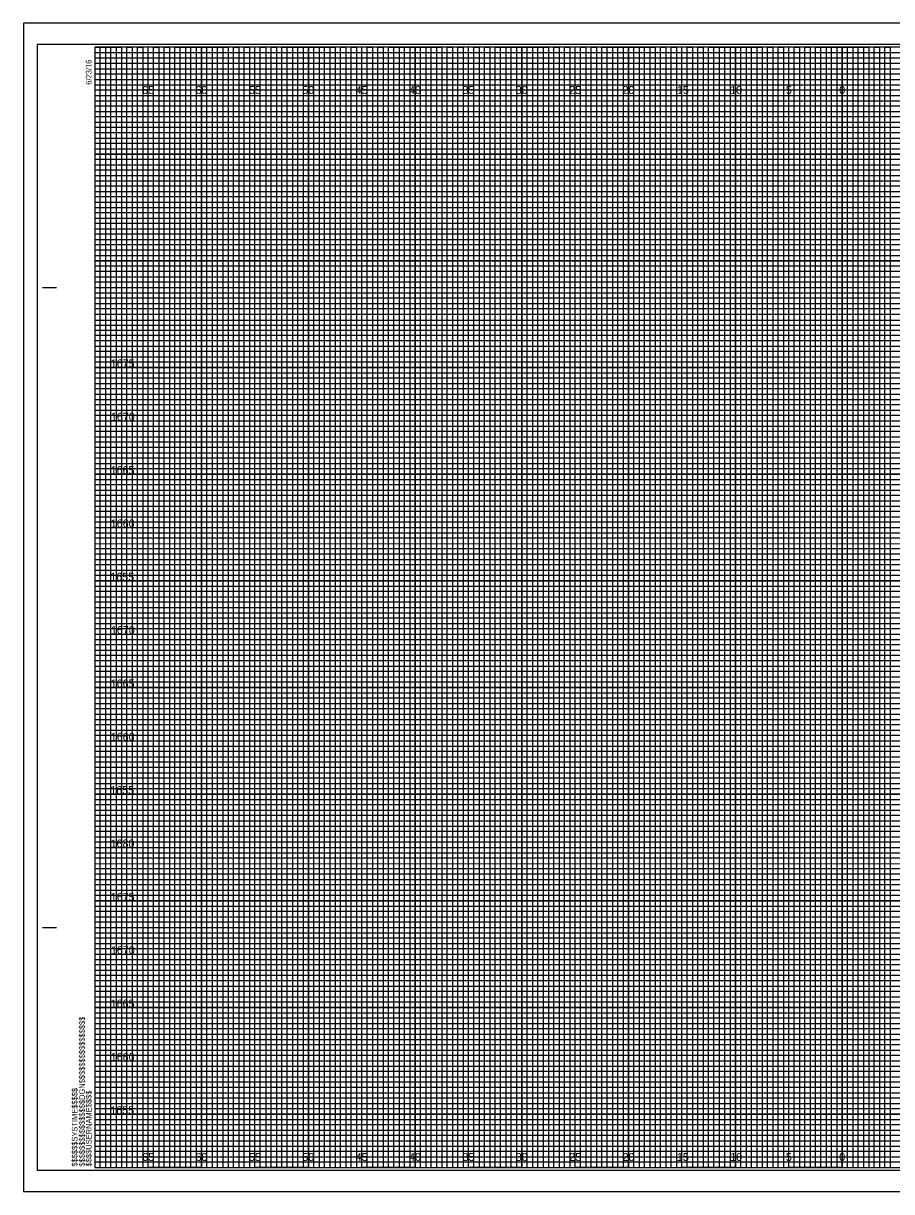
# Model space of a CAD drawing. Extents: x -73 to 95, y 6 to 446.
# Drawn here: x -73.1 to 8.2, y 116.1 to 225.6 of the extents above; entities that cross this region are included whole.
import ezdxf

# ---------------------------------------------------------------- set-up
doc = ezdxf.new("R2010")
doc.units = 0
for name, color, linetype in [('Exist CMT Alignment Centerline', 7, 'Continuous'), ('Prop Horizontal Alignment', 7, 'Continuous'), ('Prop XS DDE', 7, 'Continuous'), ('Scratch_Level_3', 7, 'Continuous'), ('Sheet Cross Section CELL', 7, 'Continuous'), ('Sheet Cross Section Grid Minor 1 CELL', 7, 'Continuous'), ('Sheet Cross Section Grid Minor 2 CELL', 7, 'Continuous'), ('Sheet Cutting Line CELL', 7, 'Continuous'), ('Sheet DOT Grid CELL', 7, 'Continuous'), ('Sheet Plot Border Inside CELL', 7, 'Continuous'), ('Sheet Plot Border Outside CELL', 7, 'Continuous')]:
    doc.layers.add(name, color=color, linetype=linetype)

msp = doc.modelspace()

# ---------------------------------------------------------------- linework, layer by layer
at = {"layer": 'Exist CMT Alignment Centerline'}
for p, q in [((-61.4, 223.4), (-66.4, 223.4)), ((-61.4, 118.4), (-61.4, 223.4)), ((-51.4, 223.4), (-56.4, 223.4)), ((-56.4, 223.4), (-56.4, 118.4)), ((-51.4, 118.4), (-51.4, 223.4)), ((-41.4, 223.4), (-46.4, 223.4)), ((-46.4, 223.4), (-46.4, 118.4)), ((-41.4, 118.4), (-41.4, 223.4)), ((-31.4, 223.4), (-36.4, 223.4)), ((-36.4, 223.4), (-36.4, 118.4)), ((-31.4, 118.4), (-31.4, 223.4)), ((-21.4, 223.4), (-26.4, 223.4)), ((-26.4, 223.4), (-26.4, 118.4)), ((-21.4, 118.4), (-21.4, 223.4)), ((-11.4, 223.4), (-16.4, 223.4)), ((-16.4, 223.4), (-16.4, 118.4)), ((-11.4, 118.4), (-11.4, 223.4)), ((-1.4, 223.4), (-6.4, 223.4)), ((-6.4, 223.4), (-6.4, 118.4)), ((-1.4, 118.4), (-1.4, 223.4)), ((8.6, 223.4), (3.6, 223.4)), ((3.6, 223.4), (3.6, 118.4)), ((-56.4, 118.4), (-61.4, 118.4)), ((-46.4, 118.4), (-51.4, 118.4)), ((-36.4, 118.4), (-41.4, 118.4)), ((-26.4, 118.4), (-31.4, 118.4)), ((-16.4, 118.4), (-21.4, 118.4)), ((-6.4, 118.4), (-11.4, 118.4)), ((3.6, 118.4), (-1.4, 118.4))]:
    msp.add_line(p, q, dxfattribs=at)
for points in [[(-66.4, 218.4), (93.6, 218.4), (93.6, 213.4), (-66.4, 213.4)], [(-66.4, 208.4), (93.6, 208.4), (93.6, 203.4), (-66.4, 203.4)], [(-66.4, 198.4), (93.6, 198.4), (93.6, 193.4), (-66.4, 193.4)], [(-66.4, 188.4), (93.6, 188.4), (93.6, 183.4), (-66.4, 183.4)], [(-66.4, 178.4), (93.6, 178.4), (93.6, 173.4), (-66.4, 173.4)], [(-66.4, 168.4), (93.6, 168.4), (93.6, 163.4), (-66.4, 163.4)], [(-66.4, 158.4), (93.6, 158.4), (93.6, 153.4), (-66.4, 153.4)], [(-66.4, 148.4), (93.6, 148.4), (93.6, 143.4), (-66.4, 143.4)], [(-66.4, 138.4), (93.6, 138.4), (93.6, 133.4), (-66.4, 133.4)], [(-66.4, 128.4), (93.6, 128.4), (93.6, 123.4), (-66.4, 123.4)]]:
    msp.add_lwpolyline(points, dxfattribs=at)
at = {"layer": 'Prop XS DDE'}
for points in [[(-66.4, 223.4), (-63.9, 223.4), (-63.9, 118.4), (-58.9, 118.4), (-58.9, 223.4), (-53.9, 223.4), (-53.9, 118.4), (-48.9, 118.4), (-48.9, 223.4), (-43.9, 223.4), (-43.9, 118.4), (-38.9, 118.4), (-38.9, 223.4), (-33.9, 223.4), (-33.9, 118.4), (-28.9, 118.4), (-28.9, 223.4), (-23.9, 223.4), (-23.9, 118.4), (-18.9, 118.4), (-18.9, 223.4), (-13.9, 223.4), (-13.9, 118.4), (-8.9, 118.4), (-8.9, 223.4), (-3.9, 223.4), (-3.9, 118.4), (1.1, 118.4), (1.1, 223.4), (6.1, 223.4), (6.1, 118.4), (11.1, 118.4)], [(-66.4, 220.9), (71.1, 220.9)], [(-66.4, 210.9), (93.6, 210.9), (93.6, 215.9), (-66.4, 215.9)], [(-66.4, 200.9), (93.6, 200.9), (93.6, 205.9), (-66.4, 205.9)], [(-66.4, 190.9), (93.6, 190.9), (93.6, 195.9), (-66.4, 195.9)], [(-66.4, 180.9), (93.6, 180.9), (93.6, 185.9), (-66.4, 185.9)], [(-66.4, 170.9), (93.6, 170.9), (93.6, 175.9), (-66.4, 175.9)], [(-66.4, 160.9), (93.6, 160.9), (93.6, 165.9), (-66.4, 165.9)], [(-66.4, 150.9), (93.6, 150.9), (93.6, 155.9), (-66.4, 155.9)], [(-66.4, 140.9), (93.6, 140.9), (93.6, 145.9), (-66.4, 145.9)], [(-66.4, 130.9), (93.6, 130.9), (93.6, 135.9), (-66.4, 135.9)], [(-66.4, 120.9), (93.6, 120.9), (93.6, 125.9), (-66.4, 125.9)]]:
    msp.add_lwpolyline(points, dxfattribs=at)
at = {"layer": 'Sheet Cross Section CELL'}
for p, q in [((-71.3, 200.9), (-70.05, 200.9)), ((-71.25, 200.9), (-70, 200.9)), ((-71.3, 140.9), (-70.05, 140.9)), ((-71.25, 140.9), (-70, 140.9)), ((-66.4, 118.4), (-66.4, 118.4)), ((-66.4, 118.4), (-66.4, 118.4)), ((-66.4, 118.4), (-66.4, 118.4)), ((-66.4, 118.4), (-66.4, 118.4)), ((-66.4, 118.4), (-66.4, 118.4)), ((-66.4, 118.4), (-66.4, 118.4)), ((-66.4, 118.4), (-66.4, 118.4))]:
    msp.add_line(p, q, dxfattribs=at)
msp.add_lwpolyline([(93.6, 223.4), (-66.4, 223.4), (-66.4, 118.4), (93.6, 118.4)], close=True, dxfattribs=at)
at = {"layer": 'Sheet Cross Section Grid Minor 1 CELL'}
for p, q in [((-66.4, 222.9), (63.6, 222.9)), ((63.6, 222.39), (-66.4, 222.39)), ((-66.4, 222.39), (-66.4, 221.9)), ((-66.4, 221.9), (63.6, 221.9)), ((63.6, 221.34), (-66.4, 221.34)), ((-66.4, 221.34), (-66.4, 220.4)), ((-66.4, 220.4), (93.6, 220.4))]:
    msp.add_line(p, q, dxfattribs=at)
for points in [[(-66.4, 219.9), (68.6, 219.9), (93.6, 219.9), (93.6, 219.4), (-66.4, 219.4)], [(-66.4, 218.9), (93.6, 218.9), (93.6, 217.9), (-66.4, 217.9)], [(-66.4, 217.4), (93.6, 217.4), (93.6, 216.9), (-66.4, 216.89)], [(-66.4, 216.4), (93.6, 216.4), (93.6, 215.4), (-66.4, 215.4)], [(-66.4, 214.9), (93.6, 214.9), (93.6, 214.4), (-66.4, 214.4)], [(-66.4, 213.9), (93.6, 213.9), (93.6, 212.9), (-66.4, 212.9)], [(-66.4, 212.4), (93.6, 212.4), (93.6, 211.9), (-66.4, 211.9)], [(-66.4, 211.4), (93.6, 211.4), (93.6, 210.4), (-66.4, 210.4)], [(-66.4, 209.9), (93.6, 209.9), (93.6, 209.4), (-66.4, 209.4)], [(-66.4, 208.9), (93.6, 208.9), (93.6, 207.9), (-66.4, 207.9)], [(-66.4, 207.4), (93.6, 207.4), (93.6, 206.9), (-66.4, 206.9)], [(-66.4, 206.4), (93.6, 206.4), (93.6, 205.37), (93.6, 204.9), (93.6, 204.4), (-66.4, 204.4)], [(-66.4, 205.4), (93.6, 205.4), (93.6, 204.9), (-66.4, 204.9)], [(-66.4, 203.9), (93.6, 203.9), (93.6, 202.9), (-66.4, 202.91)], [(-66.4, 202.91), (93.6, 202.9), (93.6, 202.4), (-66.4, 202.4)], [(-66.4, 201.9), (93.6, 201.9), (93.6, 201.4), (-66.4, 201.4)], [(-66.4, 200.4), (93.6, 200.4), (93.6, 199.9), (-66.4, 199.9)], [(-66.4, 199.4), (93.6, 199.4), (93.6, 198.9), (-66.4, 198.9)], [(-66.43, 197.84), (93.6, 197.84), (93.6, 197.34), (-66.43, 197.34)], [(-66.4, 196.9), (93.6, 196.9), (93.6, 196.4), (-66.4, 196.4)], [(-66.4, 195.4), (93.6, 195.4), (93.6, 194.9), (-66.4, 194.9)], [(-66.4, 194.4), (93.6, 194.4), (93.6, 193.9), (-66.4, 193.9)], [(-66.4, 192.9), (93.6, 192.9), (93.6, 192.4), (-66.4, 192.4)], [(-66.4, 191.9), (93.6, 191.9), (93.6, 191.4), (-66.4, 191.4)], [(-66.4, 190.4), (93.6, 190.4), (93.6, 189.9), (-66.4, 189.9)], [(-66.4, 189.4), (93.6, 189.4), (93.6, 188.9), (-66.4, 188.9)], [(-66.4, 187.9), (93.6, 187.9), (93.6, 187.39), (-66.4, 187.4)], [(-66.4, 186.9), (93.6, 186.9), (93.6, 186.4), (-66.4, 186.4)], [(-66.4, 185.4), (93.6, 185.4), (93.6, 184.9), (-66.4, 184.9)], [(-66.4, 184.4), (93.6, 184.4), (93.6, 183.9), (-66.4, 183.9)], [(-66.4, 182.9), (93.6, 182.9), (93.6, 182.4), (-66.4, 182.4)], [(-66.4, 181.9), (93.6, 181.9), (93.6, 181.4), (-66.4, 181.4)], [(-66.4, 180.4), (93.6, 180.4), (93.6, 179.9), (-66.4, 179.9)], [(-66.4, 179.4), (93.6, 179.4), (93.6, 178.9), (-66.4, 178.9)], [(-66.4, 177.9), (93.6, 177.9), (93.6, 177.4), (-66.4, 177.4)], [(-66.4, 176.89), (93.64, 176.85), (93.6, 176.4), (-66.4, 176.4)], [(-66.4, 175.4), (93.6, 175.4), (93.6, 174.9), (-66.4, 174.9)], [(-66.4, 174.4), (93.6, 174.4), (93.6, 173.9), (-66.4, 173.9)], [(-66.4, 172.9), (93.6, 172.9), (93.6, 172.4), (-66.4, 172.4)], [(-66.4, 171.9), (93.6, 171.9), (93.6, 171.4), (-66.4, 171.4)], [(-66.4, 170.4), (93.6, 170.4), (93.6, 169.9), (-66.4, 169.9)], [(-66.4, 169.4), (93.6, 169.4), (93.6, 168.9), (-66.4, 168.9)], [(-66.4, 167.9), (93.6, 167.9), (93.6, 167.4), (-66.4, 167.4)], [(-66.4, 166.9), (93.6, 166.9), (93.6, 166.4), (-66.4, 166.4)], [(-66.4, 165.4), (93.6, 165.4), (93.6, 164.9), (-66.4, 164.9)], [(-66.4, 164.4), (93.6, 164.4), (93.6, 163.9), (-66.4, 163.9)], [(-66.4, 162.9), (93.6, 162.9), (93.6, 162.4), (-66.4, 162.4)], [(-66.4, 161.9), (93.6, 161.9), (93.6, 161.4), (-66.4, 161.4)], [(-66.4, 160.4), (93.6, 160.4), (93.6, 159.9), (-66.4, 159.9)], [(-66.4, 159.4), (93.6, 159.4), (93.6, 158.9), (-66.4, 158.9)], [(-66.4, 157.9), (93.6, 157.9), (93.6, 157.39), (-66.4, 157.4)], [(-66.4, 156.9), (93.6, 156.9), (93.6, 156.4), (-66.4, 156.4)], [(-66.4, 155.4), (93.6, 155.4), (93.6, 154.9), (-66.4, 154.9)], [(-66.4, 154.4), (93.6, 154.4), (93.6, 153.9), (-66.4, 153.9)], [(-66.4, 152.9), (93.6, 152.9), (93.6, 152.4), (-66.4, 152.4)], [(-66.4, 151.9), (93.6, 151.9), (93.6, 151.4), (-66.4, 151.4)], [(-66.4, 150.4), (93.6, 150.4), (93.6, 149.9), (-66.4, 149.9)], [(-66.4, 149.4), (93.6, 149.4), (93.6, 148.9), (-66.4, 148.9)], [(-66.4, 147.9), (93.6, 147.9), (93.6, 147.4), (-66.4, 147.4)], [(-66.4, 146.89), (93.64, 146.85), (93.6, 146.4), (-66.4, 146.4)], [(-66.4, 145.4), (93.6, 145.4), (93.6, 144.9), (-66.4, 144.9)], [(-66.4, 144.4), (93.6, 144.4), (93.6, 143.9), (-66.4, 143.9)], [(-66.4, 142.9), (93.6, 142.9), (93.6, 142.4), (-66.4, 142.4)], [(-66.4, 141.9), (93.6, 141.9), (93.6, 141.4), (-66.4, 141.4)], [(-66.4, 140.4), (93.6, 140.4), (93.6, 139.9), (-66.4, 139.9)], [(-66.4, 139.4), (93.6, 139.4), (93.6, 138.9), (-66.4, 138.9)], [(-66.4, 137.9), (93.6, 137.9), (93.6, 137.4), (-66.4, 137.4)], [(-66.4, 136.9), (93.6, 136.9), (93.6, 136.4), (-66.4, 136.4)], [(-66.4, 135.4), (93.6, 135.4), (93.6, 134.9), (-66.4, 134.9)], [(-66.4, 134.4), (93.6, 134.4), (93.6, 133.9), (-66.4, 133.9)], [(-66.4, 132.9), (93.6, 132.9), (93.6, 132.4), (-66.4, 132.4)], [(-66.4, 131.9), (93.6, 131.9), (93.6, 131.4), (-66.4, 131.4)], [(-66.4, 130.4), (93.6, 130.4), (93.6, 129.9), (-66.4, 129.9)], [(-66.4, 129.4), (93.6, 129.4), (93.6, 128.9), (-66.4, 128.9)], [(-66.4, 127.9), (93.6, 127.9), (93.6, 127.4), (-66.4, 127.4)], [(-66.4, 126.9), (93.6, 126.9), (93.6, 126.4), (-66.4, 126.4)], [(-66.4, 125.4), (93.6, 125.4), (93.6, 124.9), (-66.4, 124.9)], [(-66.4, 124.4), (93.6, 124.4), (93.6, 123.9), (-66.4, 123.9)], [(-66.4, 122.9), (93.6, 122.9), (93.6, 122.4), (-66.4, 122.4)], [(-66.4, 121.9), (93.6, 121.9), (93.6, 121.4), (-66.4, 121.4)], [(-66.4, 120.4), (93.6, 120.4), (93.6, 119.9), (-66.4, 119.9)], [(-66.4, 119.4), (93.6, 119.4), (93.6, 118.9), (-66.4, 118.9)]]:
    msp.add_lwpolyline(points, dxfattribs=at)
at = {"layer": 'Sheet Cross Section Grid Minor 2 CELL'}
for points in [[(-66.4, 118.4), (-65.9, 118.4), (-65.9, 223.4), (-65.4, 223.4), (-65.4, 118.4)], [(-65.4, 118.4), (-64.9, 118.4), (-64.9, 223.4), (-64.4, 223.4), (-64.4, 118.4)], [(-63.9, 118.4), (-63.4, 118.4), (-63.4, 223.4), (-62.9, 223.4), (-62.9, 118.4)], [(-62.9, 118.4), (-62.4, 118.4), (-62.4, 223.4), (-61.9, 223.4), (-61.9, 118.4)], [(-61.4, 118.4), (-60.9, 118.4), (-60.9, 223.4), (-60.4, 223.4), (-60.4, 118.4)], [(-60.4, 118.4), (-59.9, 118.4), (-59.9, 223.4), (-59.4, 223.4), (-59.4, 118.4)], [(-58.9, 118.4), (-58.4, 118.4), (-58.4, 223.4), (-57.9, 223.4), (-57.9, 118.4)], [(-57.9, 118.4), (-57.4, 118.4), (-57.4, 223.4), (-56.9, 223.4), (-56.9, 118.4)], [(-56.4, 118.4), (-55.9, 118.4), (-55.9, 223.4), (-55.4, 223.4), (-55.4, 118.4)], [(-55.4, 118.4), (-54.9, 118.4), (-54.9, 223.4), (-54.4, 223.4), (-54.4, 118.4)], [(-53.9, 118.4), (-53.4, 118.4), (-53.4, 223.4), (-52.9, 223.4), (-52.9, 118.4)], [(-52.9, 118.4), (-52.4, 118.4), (-52.4, 223.4), (-51.9, 223.4), (-51.9, 118.4)], [(-51.4, 118.4), (-50.9, 118.4), (-50.9, 223.4), (-50.4, 223.4), (-50.4, 118.4)], [(-50.4, 118.4), (-49.9, 118.4), (-49.9, 223.4), (-49.4, 223.4), (-49.4, 118.4)], [(-48.9, 118.4), (-48.4, 118.4), (-48.4, 223.4), (-47.9, 223.4), (-47.9, 118.4)], [(-47.9, 118.4), (-47.4, 118.4), (-47.4, 223.4), (-46.9, 223.4), (-46.9, 118.4)], [(-46.4, 118.4), (-45.9, 118.4), (-45.9, 223.4), (-45.4, 223.4), (-45.4, 118.4)], [(-45.4, 118.4), (-44.9, 118.4), (-44.9, 223.4), (-44.4, 223.4), (-44.4, 118.4)], [(-43.9, 118.4), (-43.4, 118.4), (-43.4, 223.4), (-42.9, 223.4), (-42.9, 118.4)], [(-42.9, 118.4), (-42.4, 118.4), (-42.4, 223.4), (-41.9, 223.4), (-41.9, 118.4)], [(-41.4, 118.4), (-40.9, 118.4), (-40.9, 223.4), (-40.4, 223.4), (-40.4, 118.4)], [(-40.4, 118.4), (-39.9, 118.4), (-39.9, 223.4), (-39.4, 223.4), (-39.4, 118.4)], [(-38.9, 118.4), (-38.4, 118.4), (-38.4, 223.4), (-37.9, 223.4), (-37.9, 118.4)], [(-37.9, 118.4), (-37.4, 118.4), (-37.4, 223.4), (-36.9, 223.4), (-36.9, 118.4)], [(-36.4, 118.4), (-35.9, 118.4), (-35.9, 223.4), (-35.4, 223.4), (-35.4, 118.4)], [(-35.4, 118.4), (-34.9, 118.4), (-34.9, 223.4), (-34.4, 223.4), (-34.4, 118.4)], [(-33.9, 118.4), (-33.4, 118.4), (-33.4, 223.4), (-32.9, 223.4), (-32.9, 118.4)], [(-32.9, 118.4), (-32.4, 118.4), (-32.4, 223.4), (-31.9, 223.4), (-31.9, 118.4)], [(-31.4, 118.4), (-30.9, 118.4), (-30.9, 223.4), (-30.4, 223.4), (-30.4, 118.4)], [(-30.4, 118.4), (-29.9, 118.4), (-29.9, 223.4), (-29.4, 223.4), (-29.4, 118.4)], [(-28.9, 118.4), (-28.4, 118.4), (-28.4, 223.4), (-27.9, 223.4), (-27.9, 118.4)], [(-27.9, 118.4), (-27.4, 118.4), (-27.4, 223.4), (-26.9, 223.4), (-26.9, 118.4)], [(-26.4, 118.4), (-25.9, 118.4), (-25.9, 223.4), (-25.4, 223.4), (-25.4, 118.4)], [(-25.4, 118.4), (-24.9, 118.4), (-24.9, 223.4), (-24.4, 223.4), (-24.4, 118.4)], [(-23.9, 118.4), (-23.4, 118.4), (-23.4, 223.4), (-22.9, 223.4), (-22.9, 118.4)], [(-22.9, 118.4), (-22.4, 118.4), (-22.4, 223.4), (-21.9, 223.4), (-21.9, 118.4)], [(-21.4, 118.4), (-20.9, 118.4), (-20.9, 223.4), (-20.4, 223.4), (-20.4, 118.4)], [(-20.4, 118.4), (-19.9, 118.4), (-19.9, 223.4), (-19.4, 223.4), (-19.4, 118.4)], [(-18.9, 118.4), (-18.4, 118.4), (-18.4, 223.4), (-17.9, 223.4), (-17.9, 118.4)], [(-17.9, 118.4), (-17.4, 118.4), (-17.4, 223.4), (-16.9, 223.4), (-16.9, 118.4)], [(-16.4, 118.4), (-15.9, 118.4), (-15.9, 223.4), (-15.4, 223.4), (-15.4, 118.4)], [(-15.4, 118.4), (-14.9, 118.4), (-14.9, 223.4), (-14.4, 223.4), (-14.4, 118.4)], [(-13.9, 118.4), (-13.4, 118.4), (-13.4, 223.4), (-12.9, 223.4), (-12.9, 118.4)], [(-12.9, 118.4), (-12.4, 118.4), (-12.4, 223.4), (-11.9, 223.4), (-11.9, 118.4)], [(-11.4, 118.4), (-10.9, 118.4), (-10.9, 223.4), (-10.4, 223.4), (-10.4, 118.4)], [(-10.4, 118.4), (-9.9, 118.4), (-9.9, 223.4), (-9.4, 223.4), (-9.4, 118.4)], [(-8.9, 118.4), (-8.4, 118.4), (-8.4, 223.4), (-7.9, 223.4), (-7.9, 118.4)], [(-7.9, 118.4), (-7.4, 118.4), (-7.4, 223.4), (-6.9, 223.4), (-6.9, 118.4)], [(-6.4, 118.4), (-5.9, 118.4), (-5.9, 223.4), (-5.4, 223.4), (-5.4, 118.4)], [(-5.4, 118.4), (-4.9, 118.4), (-4.9, 223.4), (-4.4, 223.4), (-4.4, 118.4)], [(-3.9, 118.4), (-3.4, 118.4), (-3.4, 223.4), (-2.9, 223.4), (-2.9, 118.4)], [(-2.9, 118.4), (-2.4, 118.4), (-2.4, 223.4), (-1.9, 223.4), (-1.9, 118.4)], [(-1.4, 118.4), (-0.9, 118.4), (-0.9, 223.4), (-0.4, 223.4), (-0.4, 118.4)], [(-0.4, 118.4), (0.1, 118.4), (0.1, 223.4), (0.6, 223.4), (0.6, 118.4)], [(1.1, 118.4), (1.6, 118.4), (1.6, 223.4), (2.1, 223.4), (2.1, 118.4)], [(2.1, 118.4), (2.6, 118.4), (2.6, 223.4), (3.1, 223.4), (3.1, 118.4)], [(3.6, 118.4), (4.1, 118.4), (4.1, 223.4), (4.6, 223.4), (4.6, 118.4)], [(4.6, 118.4), (5.1, 118.4), (5.1, 223.4), (5.6, 223.4), (5.6, 118.4)], [(6.1, 118.4), (6.6, 118.4), (6.6, 223.4), (7.1, 223.4), (7.1, 118.4)], [(7.1, 118.4), (7.6, 118.4), (7.6, 223.4), (8.1, 223.4), (8.1, 118.4)]]:
    msp.add_lwpolyline(points, dxfattribs=at)
at = {"layer": 'Sheet Cutting Line CELL'}
for p, q in [((95.25, 225.65), (-73.1, 225.65)), ((-73.1, 225.65), (-73.1, 116.15)), ((-73.1, 116.15), (95.25, 116.15))]:
    msp.add_line(p, q, dxfattribs=at)
at = {"layer": 'Sheet DOT Grid CELL'}
for p, q in [((-61.4, 118.4), (-61.4, 223.4)), ((-56.4, 118.4), (-56.4, 223.4)), ((-51.4, 118.4), (-51.4, 223.4)), ((-46.4, 118.4), (-46.4, 223.4)), ((-41.4, 118.4), (-41.4, 223.4)), ((-36.4, 118.4), (-36.4, 223.4)), ((-31.4, 118.4), (-31.4, 223.4)), ((-26.4, 118.4), (-26.4, 223.4)), ((-21.4, 118.4), (-21.4, 223.4)), ((-16.4, 118.4), (-16.4, 223.4)), ((-11.4, 118.4), (-11.4, 223.4)), ((-6.4, 118.4), (-6.4, 223.4)), ((-1.4, 118.4), (-1.4, 223.4)), ((3.6, 118.4), (3.6, 223.4)), ((-66.4, 218.4), (93.6, 218.4)), ((-66.4, 213.4), (93.6, 213.4)), ((-66.4, 208.4), (93.6, 208.4)), ((-66.4, 203.4), (93.6, 203.4)), ((-66.4, 198.4), (93.6, 198.4)), ((-66.4, 193.4), (93.6, 193.4)), ((-66.4, 188.4), (93.6, 188.4)), ((-66.4, 183.4), (93.6, 183.4)), ((-66.4, 178.4), (93.6, 178.4)), ((-66.4, 173.4), (93.6, 173.4)), ((-66.4, 168.4), (93.6, 168.4)), ((-66.4, 163.4), (93.6, 163.4)), ((-66.4, 158.4), (93.6, 158.4)), ((-66.4, 153.4), (93.6, 153.4)), ((-66.4, 148.4), (93.6, 148.4)), ((-66.4, 143.4), (93.6, 143.4)), ((-66.4, 138.4), (93.6, 138.4)), ((-66.4, 133.4), (93.6, 133.4)), ((-66.4, 128.4), (93.6, 128.4)), ((-66.4, 123.4), (93.6, 123.4))]:
    msp.add_line(p, q, dxfattribs=at)
at = {"layer": 'Sheet Plot Border Inside CELL'}
msp.add_lwpolyline([(-71.8, 118.15), (94.8, 118.15), (94.8, 223.65), (-71.8, 223.65)], close=True, dxfattribs=at)
at = {"layer": 'Sheet Plot Border Outside CELL'}
msp.add_lwpolyline([(-73.1, 116.15), (95.25, 116.15), (95.25, 225.65), (-73.1, 225.65)], close=True, dxfattribs=at)

# ---------------------------------------------------------------- texts
at = {"layer": 'Prop Horizontal Alignment'}
for s, p in [('1675', (-64.91, 193.4)), ('1670', (-64.9, 188.4)), ('1665', (-64.92, 183.4)), ('1660', (-64.91, 178.4)), ('1655', (-64.95, 173.4)), ('1670', (-64.9, 168.4)), ('1665', (-64.92, 163.4)), ('1660', (-64.91, 158.4)), ('1655', (-64.95, 153.4)), ('1680', (-64.93, 148.4)), ('1675', (-64.91, 143.4)), ('1670', (-64.9, 138.4)), ('1665', (-64.92, 133.4)), ('1660', (-64.91, 128.4)), ('1655', (-64.95, 123.4))]:
    msp.add_text(s, height=0.75, dxfattribs=at).set_placement(p)
at = {"layer": 'Scratch_Level_3'}
for s, p in [('65', (-61.96, 219.02)), ('60', (-56.97, 219.02)), ('55', (-51.96, 219.02)), ('50', (-46.97, 219.02)), ('45', (-41.96, 219.02)), ('40', (-36.97, 219.02)), ('35', (-31.96, 219.02)), ('30', (-26.97, 219.02)), ('25', (-21.96, 219.02)), ('20', (-16.97, 219.02)), ('15', (-11.87, 219.02)), ('10', (-6.88, 219.02)), ('5', (-1.66, 219.02)), ('0', (3.33, 219.02)), ('0', (3.33, 219.02)), ('65', (-61.96, 119.02)), ('60', (-56.97, 119.02)), ('55', (-51.96, 119.02)), ('50', (-46.97, 119.02)), ('45', (-41.96, 119.02)), ('40', (-36.97, 119.02)), ('35', (-31.96, 119.02)), ('30', (-26.97, 119.02)), ('25', (-21.96, 119.02)), ('20', (-16.97, 119.02)), ('15', (-11.87, 119.02)), ('10', (-6.88, 119.02)), ('5', (-1.66, 119.02)), ('0', (3.33, 119.02)), ('0', (3.33, 119.02))]:
    msp.add_text(s, height=0.75, dxfattribs=at).set_placement(p)
at = {"layer": 'Sheet Cross Section CELL'}
for s, p in [('6/23/16', (-66.72, 219.9)), ('$$$$$$$$$$$$$$$$DGN$$$$$$$$$$$$$$$$', (-67.34, 118.49)), ('$$$$$$SYSTIME$$$$$', (-68.03, 118.49)), ('$$$$USERNAME$$$$', (-66.71, 118.51))]:
    msp.add_text(s, height=0.525, rotation=90, dxfattribs=at).set_placement(p)

doc.saveas('drawing.dxf')
